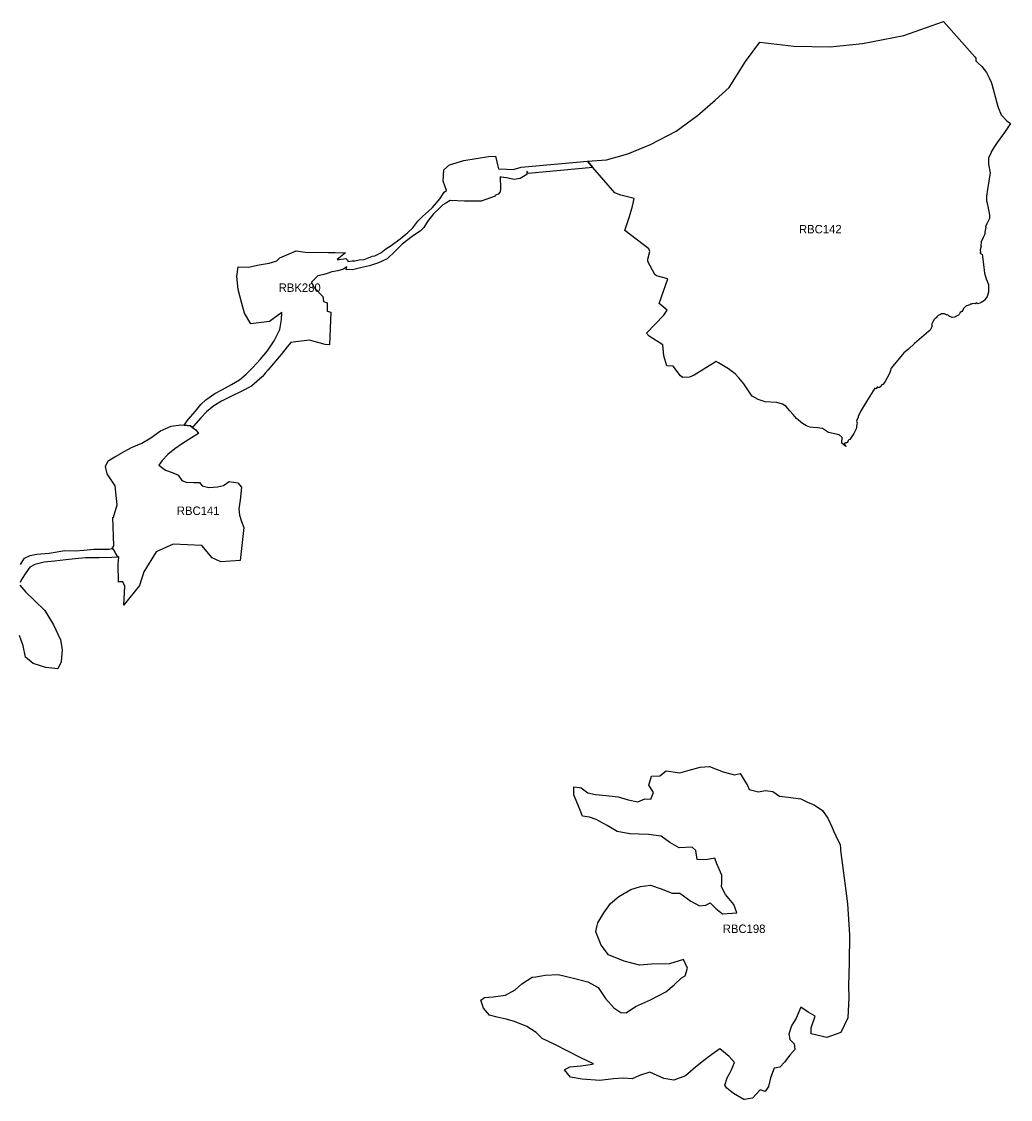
# Model space of a CAD drawing. Extents: x -559776 to -467147, y -1204122 to -1132159.
# Drawn here: x -494859 to -489001, y -1181970 to -1175586 of the extents above; entities that cross this region are included whole.
import ezdxf

# ---------------------------------------------------------------- set-up
doc = ezdxf.new("R2010")
doc.units = 0
doc.layers.add('regionalni_biocentrum_biokoridor', color=7, linetype='Continuous')

msp = doc.modelspace()

# ---------------------------------------------------------------- linework, layer by layer
at = {"layer": 'regionalni_biocentrum_biokoridor'}
for points in [[(-489211.5, -1175795.62), (-489205.84, -1175802), (-489205.56, -1175819.25), (-489195.72, -1175828), (-489169.91, -1175851.12), (-489142.31, -1175887.25), (-489126.97, -1175919.5), (-489115.41, -1175943.87), (-489111.56, -1175957.5), (-489080.97, -1176066.56), (-489073, -1176095), (-489056.19, -1176139), (-489023.22, -1176174.5), (-489001.15, -1176189.82), (-489008.86, -1176201.49), (-489028.36, -1176231.04), (-489040.39, -1176249.29), (-489041.72, -1176251.22), (-489079.75, -1176302.12), (-489095, -1176326.5), (-489114.72, -1176357.87), (-489117.26, -1176367.32), (-489125.24, -1176381.57), (-489131.07, -1176395.91), (-489130.38, -1176430.34), (-489121.51, -1176480.99), (-489136.5, -1176580.62), (-489142.31, -1176619.37), (-489142.31, -1176647.5), (-489137.85, -1176669.25), (-489137.89, -1176671.59), (-489135.84, -1176679.07), (-489124.81, -1176732.87), (-489124.81, -1176751.87), (-489139.42, -1176780.54), (-489139.62, -1176780.77), (-489140.72, -1176783.1), (-489146.34, -1176794.12), (-489146.52, -1176795.33), (-489149.35, -1176801.3), (-489147.64, -1176802.83), (-489152.09, -1176832.62), (-489153.75, -1176843.62), (-489155.81, -1176848.62), (-489162.5, -1176864.5), (-489173.94, -1176890.62), (-489175.94, -1176913.87), (-489175.56, -1176916.78), (-489180.03, -1176938.37), (-489179.33, -1176955.43), (-489181.58, -1176957.48), (-489177.71, -1176959.46), (-489169.99, -1176962.87), (-489169.42, -1176964.3), (-489161.59, -1177024.87), (-489155.09, -1177075.37), (-489145.69, -1177109.62), (-489139.72, -1177123.5), (-489131.53, -1177142.62), (-489130.19, -1177182.37), (-489132.09, -1177188.75), (-489139.41, -1177213.37), (-489152.72, -1177234.37), (-489154.91, -1177237.87), (-489174.41, -1177250.12), (-489182.97, -1177253.12), (-489195.6, -1177257.46), (-489203.55, -1177252.32), (-489210.63, -1177257.33), (-489227.42, -1177256.44), (-489231.65, -1177259.27), (-489237.36, -1177259.25), (-489241.43, -1177264.6), (-489249.04, -1177266.4), (-489254.47, -1177267.25), (-489261.84, -1177270.12), (-489265.25, -1177271.5), (-489276.69, -1177283.12), (-489286.06, -1177297.87), (-489289.12, -1177302.67), (-489299.21, -1177309.3), (-489304.9, -1177321.67), (-489308.97, -1177325.37), (-489320.75, -1177331.5), (-489327.81, -1177335.12), (-489332.37, -1177335.87), (-489347.31, -1177338.25), (-489363.47, -1177330.87), (-489366.49, -1177329.4), (-489372.43, -1177322.06), (-489376.27, -1177324.64), (-489391.06, -1177317.37), (-489409.22, -1177317.37), (-489415.31, -1177320.12), (-489430.09, -1177326.62), (-489437.09, -1177335.12), (-489440.78, -1177339.64), (-489442.87, -1177340.2), (-489452.66, -1177349.63), (-489462.62, -1177368.79), (-489467.12, -1177376.94), (-489466.83, -1177392.29), (-489469.25, -1177397.62), (-489476.91, -1177414.37), (-489485.78, -1177422), (-489568.5, -1177493.12), (-489605.94, -1177525.37), (-489633.19, -1177548.87), (-489660.25, -1177581.62), (-489707.44, -1177638.87), (-489714.37, -1177658.25), (-489718.53, -1177669.87), (-489743.44, -1177716.87), (-489756.96, -1177734.95), (-489760.4, -1177736.65), (-489762.65, -1177737.76), (-489772.34, -1177750.13), (-489775.26, -1177752.3), (-489782.68, -1177754.08), (-489786.5, -1177752.14), (-489791.33, -1177751.83), (-489795.75, -1177760.92), (-489796.05, -1177761.46), (-489803.56, -1177758.12), (-489805, -1177757.5), (-489853.78, -1177836.87), (-489889.09, -1177895), (-489902.87, -1177925.25), (-489904.05, -1177932.5), (-489907.55, -1177936.05), (-489910.22, -1177946.29), (-489912.08, -1177951.98), (-489909.1, -1177963.4), (-489910.28, -1177970.62), (-489915.62, -1177999.75), (-489916, -1178001.87), (-489928.12, -1178026.37), (-489935.91, -1178037.62), (-489948.31, -1178055.5), (-489951.54, -1178061.06), (-489958.5, -1178062.49), (-489962.38, -1178066.79), (-489966.08, -1178079.49), (-489973.05, -1178081.26), (-489976.3, -1178081.78), (-489985.43, -1178087.37), (-489985.5, -1178089.14), (-489984.28, -1178090.88), (-489980.28, -1178093.17), (-489975.87, -1178102.41), (-489999.25, -1178082), (-489997.22, -1178048.87), (-490015.03, -1178034.5), (-490079.19, -1178019.5), (-490114.16, -1177996.25), (-490117.55, -1177995.75), (-490141.62, -1177992.25), (-490170.27, -1177989.75), (-490190.41, -1177988), (-490208.56, -1177980.62), (-490233.78, -1177966.5), (-490268, -1177936.37), (-490288.17, -1177913.62), (-490308.34, -1177890.87), (-490329.53, -1177866.75), (-490352.06, -1177852.75), (-490383.94, -1177842.87), (-490453.87, -1177838.62), (-490494.91, -1177824.62), (-490530.47, -1177803.75), (-490544.94, -1177784.25), (-490579.56, -1177732.37), (-490609.5, -1177695.37), (-490631.03, -1177672.12), (-490671.72, -1177643.12), (-490730.56, -1177607.37), (-490745.22, -1177599), (-490873.69, -1177680.25), (-490902.59, -1177692.5), (-490942.28, -1177694.37), (-490955.06, -1177685.12), (-490998.12, -1177627.12), (-491036.47, -1177624.62), (-491053.97, -1177565.87), (-491061, -1177500.75), (-491140.37, -1177449.37), (-491157.87, -1177432.25), (-491054.28, -1177324.62), (-491035.44, -1177295.25), (-491082.53, -1177254.87), (-491030.06, -1177108.75), (-491097.34, -1177091.62), (-491106.75, -1177083), (-491148.44, -1177006), (-491148.44, -1176992.5), (-491136.34, -1176948.5), (-491143.06, -1176931.37), (-491284.44, -1176822.5), (-491257.53, -1176741.37), (-491240.72, -1176679), (-491230.66, -1176633.75), (-491308.66, -1176613.5), (-491344.5, -1176600.62), (-491474.37, -1176450.53), (-491506.62, -1176413.25), (-491393.22, -1176405.37), (-491267.16, -1176369.87), (-491132.72, -1176314.75), (-490981.5, -1176235.87), (-490855.44, -1176141.37), (-490750.44, -1176050.75), (-490666.41, -1175975.87), (-490569.78, -1175822.25), (-490485.75, -1175708), (-490284.09, -1175731.62), (-490069.84, -1175735.5), (-489876.56, -1175715.87), (-489632.91, -1175668.62), (-489397.62, -1175585.87)], [(-491506.62, -1176413.25), (-491474.37, -1176450.53), (-491857.22, -1176484.87), (-491863.66, -1176473.75), (-491865.79, -1176474.25), (-491864.88, -1176491.57), (-491904.76, -1176514.53), (-491939.81, -1176520.57), (-491986.95, -1176510.9), (-492017.16, -1176507.28), (-492023.11, -1176506.43), (-492020.79, -1176576.17), (-492023.5, -1176594.5), (-492035.84, -1176608.5), (-492054.62, -1176616), (-492053.56, -1176619.46), (-492135.6, -1176648.68), (-492235.91, -1176648.68), (-492319.79, -1176645.33), (-492344.62, -1176661.12), (-492363.37, -1176671.87), (-492387.94, -1176694.12), (-492419.03, -1176724), (-492454.22, -1176769.12), (-492476.66, -1176805.25), (-492494.87, -1176824.5), (-492544.75, -1176859.75), (-492605, -1176903.37), (-492648.56, -1176948.12), (-492693.97, -1176990.37), (-492743.66, -1177014.5), (-492797.44, -1177033.12), (-492850.44, -1177045.37), (-492899.19, -1177056), (-492935.16, -1177053.75), (-492932.69, -1177039.41), (-492951.69, -1177052.75), (-492985.56, -1177062.12), (-493019.91, -1177068.5), (-493048.47, -1177078.37), (-493069.16, -1177083.75), (-493093.78, -1177090), (-493104.59, -1177091.12), (-493142.06, -1177130.22), (-493127.56, -1177158.02), (-493074.39, -1177214.82), (-493069.55, -1177243.83), (-493047.8, -1177251.08), (-493048.93, -1177300.37), (-493026.52, -1177306.96), (-493034.43, -1177500.71), (-493060.79, -1177499.39), (-493153.05, -1177473.03), (-493234.77, -1177482.25), (-493264.28, -1177486.25), (-493286.34, -1177513.12), (-493321.66, -1177557.75), (-493366.56, -1177611.62), (-493399.16, -1177649.62), (-493416.25, -1177669.12), (-493432.41, -1177687.62), (-493434, -1177689.37), (-493497.06, -1177746), (-493554.06, -1177775), (-493622.72, -1177808.25), (-493674.59, -1177834.5), (-493719.62, -1177861.37), (-493763.47, -1177896.75), (-493797.53, -1177933.87), (-493839.84, -1177982.12), (-493845.25, -1177989.75), (-493858.31, -1177980.25), (-493895.72, -1177976.5), (-493871.12, -1177942), (-493829.25, -1177893.12), (-493797.12, -1177854.87), (-493767.94, -1177825.75), (-493713.66, -1177788), (-493667.91, -1177764.5), (-493614.81, -1177736.12), (-493567, -1177707.25), (-493527.56, -1177675), (-493488.84, -1177634.75), (-493445.41, -1177588), (-493401.41, -1177535.5), (-493361.94, -1177477.37), (-493329.53, -1177410.62), (-493319.25, -1177350.62), (-493316.2, -1177308.2), (-493389.82, -1177362.26), (-493501, -1177376.77), (-493538.47, -1177313.92), (-493552.97, -1177255.91), (-493574.73, -1177172.52), (-493584.39, -1177095.17), (-493574.73, -1177038.37), (-493514.3, -1177039.58), (-493450.25, -1177027.5), (-493392.24, -1177016.62), (-493346.31, -1177003.32), (-493329.39, -1176985.2), (-493231.5, -1176942.9), (-493179.53, -1176951.36), (-493040.57, -1176953.49), (-493000.64, -1176954.11), (-492939.53, -1176955.04), (-492989.48, -1176995.57), (-492979.94, -1176994.87), (-492950.25, -1176991.62), (-492936.97, -1176989.12), (-492926.22, -1177001.62), (-492926.77, -1177006.22), (-492900, -1177003.25), (-492885.28, -1177003.37), (-492859.5, -1176996.75), (-492828.37, -1176996), (-492779.75, -1176975.25), (-492765.31, -1176973.5), (-492731.44, -1176955.25), (-492700.62, -1176931.5), (-492669.75, -1176913.12), (-492616.19, -1176873.5), (-492570.06, -1176834.37), (-492540.03, -1176807.75), (-492510.94, -1176768.62), (-492484.06, -1176740), (-492448.03, -1176709.12), (-492424.22, -1176686.62), (-492379.75, -1176634.37), (-492354.56, -1176596.12), (-492342.3, -1176586.64), (-492360.39, -1176531.45), (-492357.98, -1176464.98), (-492322.93, -1176434.76), (-492239.54, -1176408.18), (-492092.09, -1176385.21), (-492052.21, -1176384), (-492038.91, -1176433.56), (-492033.19, -1176459.09), (-491985.74, -1176460.14), (-491947.06, -1176461.35), (-491899.93, -1176448.06), (-491899.21, -1176448.5)], [(-493895.72, -1177976.5), (-493858.31, -1177980.25), (-493845.25, -1177989.75), (-493825.66, -1178003.75), (-493809.66, -1178025.12), (-493851.5, -1178050.87), (-493904.47, -1178085.37), (-493950.37, -1178115.87), (-493991.59, -1178150.25), (-494025.97, -1178185.62), (-494046.16, -1178214.12), (-494005.31, -1178242.5), (-493959.66, -1178258.37), (-493930.34, -1178271.87), (-493908.84, -1178304.87), (-493883.66, -1178313.5), (-493838.97, -1178316), (-493804.19, -1178315.37), (-493789.34, -1178335.62), (-493749.5, -1178345.75), (-493697.59, -1178342.5), (-493663.47, -1178333), (-493628.56, -1178310.5), (-493577.16, -1178317.25), (-493556.56, -1178344), (-493564.14, -1178420.53), (-493571.55, -1178472.37), (-493567.85, -1178509.4), (-493556.74, -1178546.44), (-493541.93, -1178581.62), (-493542.06, -1178582.44), (-493542.1, -1178582.75), (-493542.18, -1178583), (-493563.42, -1178776.96), (-493678.31, -1178786.7), (-493728.94, -1178761.38), (-493791.25, -1178689.33), (-493960.66, -1178681.54), (-494061.92, -1178726.33), (-494133.97, -1178845.11), (-494159.28, -1178926.9), (-494249.23, -1179037.45), (-494252.75, -1179041.79), (-494246.91, -1178930.79), (-494258.59, -1178903.53), (-494278.18, -1178905.04), (-494283.91, -1178905.48), (-494285.86, -1178798.38), (-494281.96, -1178757.49), (-494291.79, -1178752.02), (-494314.75, -1178712.75), (-494321.2, -1178707.33), (-494311.17, -1178691.28), (-494317.08, -1178521.01), (-494313.73, -1178521.28), (-494291.83, -1178448.3), (-494304.44, -1178336.62), (-494351.44, -1178265), (-494361.19, -1178221.37), (-494345.41, -1178188.37), (-494305.61, -1178164.45), (-494301.53, -1178162), (-494270.75, -1178143.5), (-494269.16, -1178142.62), (-494267.7, -1178141.83), (-494206.5, -1178108.62), (-494147, -1178082.62), (-494092.84, -1178051.25), (-494035.59, -1178009.62), (-493973.44, -1177982.62), (-493914.94, -1177974.5)], [(-490049.1, -1180378.1), (-490034.66, -1180408.12), (-490010.19, -1180462.5), (-490007.78, -1180481), (-490008.28, -1180494.25), (-489976.59, -1180735.25), (-489966.5, -1180810.87), (-489954.34, -1180995.37), (-489957.06, -1181158.12), (-489960.75, -1181297.37), (-489957.94, -1181365.87), (-489964.16, -1181487), (-490005.56, -1181574), (-490088.22, -1181603.25), (-490181.09, -1181581.5), (-490181.75, -1181545.87), (-490158.56, -1181477.37), (-490198.47, -1181453.25), (-490243.03, -1181424), (-490270.91, -1181488.12), (-490297.22, -1181534.25), (-490314.03, -1181582.87), (-490307, -1181615.37), (-490282.16, -1181639.87), (-490279.12, -1181674.5), (-490308, -1181706.75), (-490339.75, -1181748.37), (-490366.94, -1181778.75), (-490401.34, -1181784.62), (-490421.97, -1181841.5), (-490434.25, -1181893.37), (-490453.66, -1181922.5), (-490483.5, -1181913.75), (-490529.66, -1181962.5), (-490576.56, -1181969.37), (-490580, -1181969.87), (-490640.81, -1181934.25), (-490670.25, -1181911.37), (-490680.37, -1181903.37), (-490692.19, -1181884.37), (-490678.12, -1181841), (-490662.2, -1181810.73), (-490656.03, -1181799), (-490636.22, -1181751.37), (-490667.78, -1181716.5), (-490722.09, -1181670.87), (-490769.62, -1181703.75), (-490808.97, -1181733.12), (-490867.66, -1181779.5), (-490925.37, -1181829.5), (-490995.72, -1181854.87), (-491054.59, -1181846.12), (-491138.12, -1181808.12), (-491198.97, -1181827.5), (-491241.28, -1181847.37), (-491295.56, -1181844.12), (-491351.62, -1181846.87), (-491434.12, -1181857.25), (-491538.5, -1181849.87), (-491606.53, -1181838.37), (-491642.44, -1181794.87), (-491611.28, -1181777.25), (-491545.72, -1181771.12), (-491490.37, -1181762.25), (-491470.94, -1181758.37), (-491544.97, -1181722.62), (-491626, -1181682.12), (-491695.28, -1181647.12), (-491774.16, -1181608.25), (-491811.31, -1181573.5), (-491865.53, -1181538.12), (-491939.62, -1181508.75), (-491988.56, -1181494.37), (-492023.37, -1181486.75), (-492041.59, -1181482.87), (-492085.91, -1181470.25), (-492087.81, -1181469.75), (-492121.62, -1181428.62), (-492138.16, -1181382.25), (-492116.28, -1181365.87), (-492064.94, -1181361.75), (-491992.53, -1181353.12), (-491934.53, -1181320.12), (-491895.03, -1181286), (-491833.66, -1181246.62), (-491811.72, -1181243), (-491779.41, -1181237.5), (-491756.28, -1181233.62), (-491680.25, -1181229.87), (-491597.19, -1181250.25), (-491505.37, -1181272.75), (-491442.47, -1181307.75), (-491400.75, -1181371.75), (-491350.41, -1181427.37), (-491308.06, -1181455.5), (-491277.5, -1181456.12), (-491221.19, -1181419.12), (-491133.81, -1181379.62), (-491042.84, -1181331.62), (-490993.31, -1181290.5), (-490949.62, -1181249.37), (-490928.5, -1181238.37), (-490913.66, -1181192.12), (-490938.09, -1181140.25), (-491021.28, -1181166.75), (-491128.28, -1181169.12), (-491198.16, -1181175), (-491290.12, -1181151.5), (-491381.34, -1181114), (-491425.44, -1181056.62), (-491457.69, -1180978.12), (-491456.91, -1180974.75), (-491448.84, -1180938.87), (-491445.47, -1180923.87), (-491409, -1180863.87), (-491369.53, -1180810.25), (-491321.72, -1180768.5), (-491248.81, -1180725.5), (-491192.28, -1180709.12), (-491133.12, -1180700.37), (-491069.25, -1180721.62), (-491004.06, -1180748.12), (-490960.41, -1180747.37), (-490895.09, -1180795.25), (-490842.03, -1180823.25), (-490805.75, -1180819.5), (-490780.19, -1180804.5), (-490745.59, -1180839.5), (-490705.97, -1180869.87), (-490621.06, -1180863.87), (-490639.97, -1180815.75), (-490689.37, -1180755.37), (-490713.41, -1180710.12), (-490709.84, -1180684.5), (-490710.62, -1180642), (-490741.12, -1180575.12), (-490751.84, -1180541), (-490805.41, -1180549.75), (-490856.75, -1180548.12), (-490864.47, -1180494.87), (-490887.06, -1180476.62), (-490964.06, -1180479.62), (-491019.06, -1180447.37), (-491069.87, -1180411.25), (-491145.22, -1180401.62), (-491255.37, -1180396), (-491330.87, -1180382.37), (-491389.91, -1180346.75), (-491455.31, -1180311.37), (-491494.69, -1180298.25), (-491535.12, -1180291.37), (-491554.28, -1180246.12), (-491578.56, -1180185.62), (-491586.81, -1180165), (-491587.84, -1180126.11), (-491588.03, -1180118.75), (-491553.31, -1180123), (-491544.41, -1180124.12), (-491503.44, -1180153.5), (-491459.44, -1180163.25), (-491395.47, -1180169), (-491325.03, -1180176.75), (-491265.59, -1180196.12), (-491207.75, -1180207.75), (-491166.56, -1180189), (-491131.5, -1180190.62), (-491116.12, -1180152.37), (-491144.06, -1180108.25), (-491127.56, -1180054.87), (-491078.16, -1180052.37), (-491041.09, -1180022.75), (-490959.84, -1180035), (-490903.72, -1180020.12), (-490839.06, -1180001.37), (-490784.25, -1179998.25), (-490702.87, -1180029.25), (-490635.62, -1180046.75), (-490603.06, -1180039), (-490558.44, -1180110.37), (-490549.56, -1180133.75), (-490494.47, -1180147.62), (-490451.75, -1180140), (-490408.97, -1180146.25), (-490368.84, -1180173.87), (-490317.62, -1180179.87), (-490242.31, -1180189.75), (-490198.56, -1180211), (-490163.81, -1180224.25), (-490115.31, -1180257.87), (-490082.91, -1180303.37), (-490057.87, -1180359.87)]]:
    msp.add_lwpolyline(points, close=True, dxfattribs=at)
for points in [[(-494864.69, -1178802.25), (-494840.59, -1178764), (-494808.59, -1178748.12), (-494769.03, -1178739.87), (-494695.56, -1178734.12), (-494601.97, -1178718.62), (-494539.81, -1178720.87), (-494490.56, -1178716), (-494430.94, -1178711.25), (-494372.16, -1178711.37), (-494339.22, -1178710), (-494322.34, -1178706.37), (-494321.2, -1178707.33), (-494314.75, -1178712.75), (-494291.79, -1178752.02), (-494287.94, -1178758.62), (-494323.47, -1178759.75), (-494399.5, -1178762.5), (-494479.31, -1178761.12), (-494540.47, -1178768.75), (-494596.12, -1178774.5), (-494663.06, -1178781.25), (-494723.91, -1178788.37), (-494780.34, -1178800.87), (-494809.37, -1178817.75), (-494833.31, -1178850.62), (-494858.59, -1178891.37), (-494867.28, -1178908.12)], [(-494868.5, -1178924), (-494832.44, -1178964.75), (-494781.62, -1179015.12), (-494720.34, -1179074.87), (-494668.78, -1179158.25), (-494628.34, -1179247.5), (-494618.84, -1179305.62), (-494624.53, -1179379), (-494643.62, -1179418.87), (-494714.5, -1179410.62), (-494790.59, -1179387.62), (-494834.34, -1179351.25), (-494849.5, -1179284.25), (-494871.75, -1179222.75)]]:
    msp.add_lwpolyline(points, dxfattribs=at)

# ---------------------------------------------------------------- texts
for s, p in [('RBC142', (-490253.88, -1176840.48)), ('RBK280', (-493335.77, -1177186.88)), ('RBC141', (-493938.88, -1178508.14)), ('RBC198', (-490705.17, -1180984.06))]:
    msp.add_text(s, height=50, dxfattribs=at).set_placement(p)

doc.saveas('drawing.dxf')
